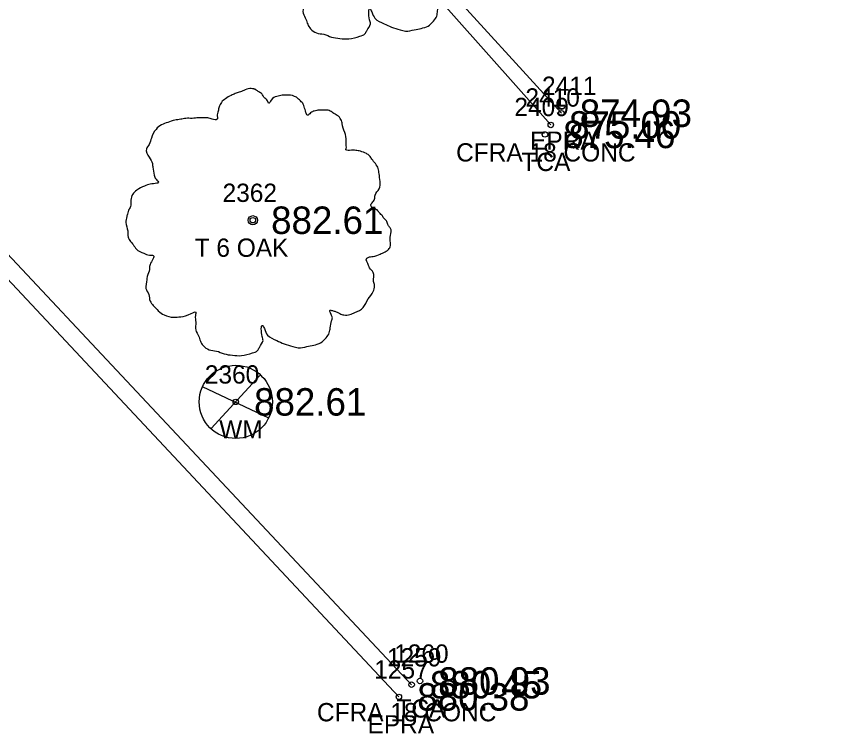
# Model space of a CAD drawing. Extents: x 1622501 to 1626664, y 1117816 to 1121579.
# Drawn here: x 1623702.07 to 1623747.27, y 1118848.61 to 1118887.8 of the extents above; entities that cross this region are included whole.
import ezdxf

# ---------------------------------------------------------------- set-up
doc = ezdxf.new("R2010")
doc.units = 0
for name, color, linetype in [('RD_EX_Conc', 7, 'Continuous'), ('RD_EX_Conc_txCode', 7, 'Continuous'), ('RD_EX_Road', 7, 'Continuous'), ('RD_EX_Road_txCode', 7, 'Continuous'), ('RD_EX_TX_Conc_ELEV', 7, 'Continuous'), ('RD_EX_TX_Road_ELEV', 7, 'Continuous'), ('RD_EX_TX_UT_ELEV', 7, 'Continuous'), ('RD_EX_TX_VEG_ELEV', 7, 'Continuous'), ('RD_EX_UT', 7, 'Continuous'), ('RD_EX_UT_txCode', 7, 'Continuous'), ('RD_EX_VEG', 7, 'Continuous'), ('RD_EX_VEG_txCode', 7, 'Continuous'), ('RD_SMD_Locator', 7, 'Continuous')]:
    doc.layers.add(name, color=color, linetype=linetype)

msp = doc.modelspace()

# ---------------------------------------------------------------- linework, layer by layer
at = {"layer": 'RD_EX_Conc'}
for points in [[(1623723.663, 1118851.276), (1623685.686, 1118891.781), (1623680.278, 1118899.276), (1623678.543, 1118902.667), (1623678.543, 1118902.667), (1623675.573, 1118911.952), (1623675.054, 1118920.354), (1623676.566, 1118930.331), (1623679.225, 1118937.184), (1623684.435, 1118944.641), (1623689.976, 1118950.418), (1623724.501, 1118984.8), (1623759.009, 1119020.42), (1623793.698, 1119055.906), (1623829.35, 1119090.862), (1623865.612, 1119125.129), (1623901.916, 1119159.181), (1623933.224, 1119188.498)], [(1623731.27, 1118881.874), (1623724.208, 1118889.844)]]:
    msp.add_lwpolyline(points, dxfattribs=at)
at = {"layer": 'RD_EX_Road'}
for points in [[(1623722.97, 1118850.612), (1623684.945, 1118891.225), (1623679.413, 1118898.675), (1623674.261, 1118911.526), (1623673.503, 1118920.185), (1623675.206, 1118930.826), (1623677.985, 1118937.822), (1623683.61, 1118945.518), (1623688.806, 1118951.265), (1623723.469, 1118985.717), (1623758.003, 1119021.43), (1623792.693, 1119056.92), (1623828.408, 1119091.915), (1623864.599, 1119126.191), (1623900.882, 1119160.216), (1623932.37, 1119189.416), (1623932.628, 1119189.219), (1623935.818, 1119192.17), (1623973.771, 1119227.767), (1623990.875, 1119243.538), (1624009.987, 1119262.018), (1624046.295, 1119296.153)], [(1623731.855, 1118882.514), (1623725.132, 1118889.887)]]:
    msp.add_lwpolyline(points, dxfattribs=at)
at = {"layer": 'RD_EX_UT'}
for p, q in [((1623712.701, 1118865.278), (1623715.369, 1118868.175)), ((1623712.22, 1118867.573), (1623715.851, 1118865.861))]:
    msp.add_line(p, q, dxfattribs=at)
msp.add_circle((1623714.054, 1118866.736), 2, dxfattribs=at)
at = {"layer": 'RD_EX_VEG'}
for centre, radius in [((1623714.985, 1118876.665), 0.25), ((1623714.973, 1118876.646), 0.0001)]:
    msp.add_circle(centre, radius, dxfattribs=at)
for points in [[(1623720.987, 1118901.145), (1623720.688, 1118901.17), (1623720.363, 1118901.07), (1623720.113, 1118900.97), (1623719.888, 1118900.895), (1623719.663, 1118900.795), (1623719.363, 1118900.62), (1623719.138, 1118900.42), (1623719.013, 1118900.17), (1623718.963, 1118899.945), (1623718.913, 1118899.671), (1623718.913, 1118899.496), (1623718.788, 1118899.471), (1623718.638, 1118899.496), (1623718.389, 1118899.571), (1623718.139, 1118899.571), (1623717.889, 1118899.571), (1623717.539, 1118899.546), (1623717.189, 1118899.546), (1623716.914, 1118899.496), (1623716.589, 1118899.446), (1623716.215, 1118899.321), (1623715.865, 1118899.196), (1623715.565, 1118898.946), (1623715.315, 1118898.471), (1623715.19, 1118898.121), (1623715.04, 1118897.871), (1623715.19, 1118897.422), (1623715.365, 1118897.072), (1623715.39, 1118896.872), (1623715.465, 1118896.447), (1623715.565, 1118896.222), (1623715.69, 1118896.022), (1623715.615, 1118895.997), (1623715.24, 1118895.947), (1623714.94, 1118895.847), (1623714.515, 1118895.622), (1623714.29, 1118895.397), (1623714.19, 1118895.073), (1623714.165, 1118894.723), (1623714.066, 1118894.523), (1623713.991, 1118894.248), (1623713.966, 1118894.173), (1623713.916, 1118893.848), (1623714.016, 1118893.398), (1623714.041, 1118893.048), (1623714.165, 1118892.824), (1623714.315, 1118892.649), (1623714.49, 1118892.399), (1623714.89, 1118892.174), (1623715.215, 1118892.074), (1623715.415, 1118892.049), (1623715.24, 1118891.549), (1623715.19, 1118891.199), (1623715.065, 1118890.799), (1623715.065, 1118890.725), (1623715.015, 1118890.25), (1623715.165, 1118889.925), (1623715.24, 1118889.55), (1623715.415, 1118889.325), (1623715.69, 1118889.025), (1623716.015, 1118888.8), (1623716.514, 1118888.675), (1623716.914, 1118888.7), (1623717.489, 1118888.875), (1623717.739, 1118888.95), (1623717.714, 1118888.775), (1623717.739, 1118888.4), (1623717.739, 1118887.976), (1623717.889, 1118887.651), (1623717.989, 1118887.376), (1623718.139, 1118887.126), (1623718.464, 1118886.901), (1623718.863, 1118886.826), (1623719.288, 1118886.676), (1623719.738, 1118886.601), (1623720.238, 1118886.576), (1623720.838, 1118886.726), (1623721.112, 1118886.851), (1623721.212, 1118887.026), (1623721.412, 1118887.401), (1623721.362, 1118887.626), (1623721.387, 1118888.226), (1623721.487, 1118888.051), (1623721.662, 1118887.701), (1623722.162, 1118887.401), (1623722.562, 1118887.226), (1623723.037, 1118887.076), (1623723.336, 1118887.001), (1623723.811, 1118887.076), (1623724.186, 1118887.151), (1623724.561, 1118887.276), (1623724.861, 1118887.551), (1623725.036, 1118887.826), (1623725.086, 1118888.101), (1623725.161, 1118888.475), (1623725.211, 1118888.65)], [(1623715.117, 1118883.832), (1623714.817, 1118883.857), (1623714.493, 1118883.757), (1623714.243, 1118883.658), (1623714.018, 1118883.583), (1623713.793, 1118883.483), (1623713.493, 1118883.308), (1623713.268, 1118883.108), (1623713.143, 1118882.858), (1623713.093, 1118882.633), (1623713.043, 1118882.358), (1623713.043, 1118882.183), (1623712.918, 1118882.158), (1623712.768, 1118882.183), (1623712.518, 1118882.258), (1623712.269, 1118882.258), (1623712.019, 1118882.258), (1623711.669, 1118882.233), (1623711.319, 1118882.233), (1623711.044, 1118882.183), (1623710.719, 1118882.133), (1623710.344, 1118882.008), (1623709.995, 1118881.883), (1623709.695, 1118881.633), (1623709.445, 1118881.159), (1623709.32, 1118880.809), (1623709.17, 1118880.559), (1623709.32, 1118880.109), (1623709.495, 1118879.759), (1623709.52, 1118879.559), (1623709.595, 1118879.135), (1623709.695, 1118878.91), (1623709.82, 1118878.71), (1623709.745, 1118878.685), (1623709.37, 1118878.635), (1623709.07, 1118878.535), (1623708.645, 1118878.31), (1623708.42, 1118878.085), (1623708.32, 1118877.76), (1623708.295, 1118877.41), (1623708.195, 1118877.21), (1623708.12, 1118876.935), (1623708.095, 1118876.86), (1623708.045, 1118876.536), (1623708.145, 1118876.086), (1623708.17, 1118875.736), (1623708.295, 1118875.511), (1623708.445, 1118875.336), (1623708.62, 1118875.086), (1623709.02, 1118874.861), (1623709.345, 1118874.761), (1623709.545, 1118874.736), (1623709.37, 1118874.237), (1623709.32, 1118873.887), (1623709.195, 1118873.487), (1623709.195, 1118873.412), (1623709.145, 1118872.937), (1623709.295, 1118872.612), (1623709.37, 1118872.238), (1623709.545, 1118872.013), (1623709.82, 1118871.713), (1623710.144, 1118871.488), (1623710.644, 1118871.363), (1623711.044, 1118871.388), (1623711.619, 1118871.563), (1623711.869, 1118871.638), (1623711.844, 1118871.463), (1623711.869, 1118871.088), (1623711.869, 1118870.663), (1623712.019, 1118870.338), (1623712.119, 1118870.063), (1623712.269, 1118869.814), (1623712.593, 1118869.589), (1623712.993, 1118869.514), (1623713.418, 1118869.364), (1623713.868, 1118869.289), (1623714.368, 1118869.264), (1623714.967, 1118869.414), (1623715.242, 1118869.539), (1623715.342, 1118869.714), (1623715.542, 1118870.088), (1623715.492, 1118870.313), (1623715.517, 1118870.913), (1623715.617, 1118870.738), (1623715.792, 1118870.388), (1623716.292, 1118870.088), (1623716.692, 1118869.914), (1623717.166, 1118869.764), (1623717.466, 1118869.689), (1623717.941, 1118869.764), (1623718.316, 1118869.839), (1623718.691, 1118869.964), (1623718.991, 1118870.238), (1623719.166, 1118870.513), (1623719.216, 1118870.788), (1623719.29, 1118871.163), (1623719.34, 1118871.338)], [(1623719.34, 1118871.338), (1623719.266, 1118871.513), (1623719.216, 1118871.763), (1623719.29, 1118871.738), (1623719.465, 1118871.688), (1623719.74, 1118871.563), (1623719.965, 1118871.488), (1623720.29, 1118871.513), (1623720.565, 1118871.613), (1623721.015, 1118871.888), (1623721.29, 1118872.362), (1623721.564, 1118872.762), (1623721.639, 1118873.087), (1623721.589, 1118873.312), (1623721.564, 1118873.812), (1623721.365, 1118874.062), (1623721.315, 1118874.187), (1623721.215, 1118874.586), (1623721.29, 1118874.636), (1623721.564, 1118874.686), (1623721.939, 1118874.811), (1623722.214, 1118874.936), (1623722.439, 1118875.111), (1623722.514, 1118875.336), (1623722.489, 1118875.736), (1623722.539, 1118876.136), (1623722.464, 1118876.286), (1623722.364, 1118876.436), (1623722.289, 1118876.636), (1623722.139, 1118876.785), (1623722.039, 1118876.935), (1623721.939, 1118877.035), (1623721.814, 1118877.185), (1623721.639, 1118877.31), (1623721.49, 1118877.36), (1623721.44, 1118877.51), (1623721.589, 1118877.71), (1623721.639, 1118877.81), (1623721.664, 1118878.035), (1623721.889, 1118878.385), (1623721.939, 1118878.785), (1623721.889, 1118879.209), (1623721.839, 1118879.484), (1623721.689, 1118879.759), (1623721.49, 1118880.009), (1623721.365, 1118880.184), (1623721.19, 1118880.309), (1623720.865, 1118880.434), (1623720.615, 1118880.484), (1623720.265, 1118880.484), (1623720.065, 1118880.534), (1623720.09, 1118880.584), (1623720.09, 1118880.734), (1623720.09, 1118881.009), (1623720.015, 1118881.458), (1623719.865, 1118881.958), (1623719.865, 1118881.983), (1623719.765, 1118882.233), (1623719.54, 1118882.433), (1623719.365, 1118882.533), (1623719.166, 1118882.658), (1623718.916, 1118882.683), (1623718.616, 1118882.683), (1623718.341, 1118882.633), (1623718.141, 1118882.533), (1623717.966, 1118882.408), (1623717.891, 1118882.558), (1623717.791, 1118882.858), (1623717.741, 1118883.008), (1623717.591, 1118883.183), (1623717.366, 1118883.383), (1623716.916, 1118883.508), (1623716.292, 1118883.433), (1623715.992, 1118883.233), (1623715.842, 1118883.058), (1623715.792, 1118883.183), (1623715.592, 1118883.383), (1623715.492, 1118883.558), (1623715.317, 1118883.683), (1623715.167, 1118883.782), (1623715.067, 1118883.832)]]:
    msp.add_spline(points, degree=3, dxfattribs=at)
at = {"layer": 'RD_SMD_Locator'}
for centre in [(1623731.855, 1118882.514), (1623731.27, 1118881.874), (1623730.951, 1118881.355), (1623714.985, 1118876.665), (1623714.054, 1118866.736), (1623723.663, 1118851.276), (1623724.12, 1118851.479), (1623722.97, 1118850.612)]:
    msp.add_circle(centre, 0.15, dxfattribs=at)

# ---------------------------------------------------------------- texts
at = {"layer": 'RD_EX_Conc_txCode'}
for s, p in [('2410', (1623729.884, 1118882.874)), ('2409', (1623729.282, 1118882.355)), ('CFRA 18 CONC', (1623726.097, 1118879.874)), ('TCA', (1623729.667, 1118879.355)), ('1260', (1623722.71, 1118852.479)), ('1259', (1623722.317, 1118852.276)), ('CFRA 18 CONC', (1623718.49, 1118849.276)), ('TCA', (1623722.836, 1118849.479))]:
    msp.add_text(s, height=1, dxfattribs=at).set_placement(p)
at = {"layer": 'RD_EX_Road_txCode'}
for s, p in [('2411', (1623730.792, 1118883.514)), ('EPRA', (1623730.138, 1118880.514)), ('1257', (1623721.624, 1118851.612)), ('EPRA', (1623721.254, 1118848.612))]:
    msp.add_text(s, height=1, dxfattribs=at).set_placement(p)
at = {"layer": 'RD_EX_TX_Conc_ELEV'}
for s, p in [('875.00', (1623732.27, 1118881.124)), ('875.46', (1623731.951, 1118880.605)), ('880.93', (1623725.12, 1118850.729)), ('880.45', (1623724.663, 1118850.526))]:
    msp.add_text(s, height=1.5, dxfattribs=at).set_placement(p)
at = {"layer": 'RD_EX_TX_Road_ELEV'}
for s, p in [('874.93', (1623732.855, 1118881.764)), ('880.38', (1623723.97, 1118849.862))]:
    msp.add_text(s, height=1.5, dxfattribs=at).set_placement(p)
at = {"layer": 'RD_EX_TX_UT_ELEV'}
msp.add_text('882.61', height=1.5, dxfattribs=at).set_placement((1623715.054, 1118865.986))
at = {"layer": 'RD_EX_TX_VEG_ELEV'}
msp.add_text('882.61', height=1.5, dxfattribs=at).set_placement((1623715.985, 1118875.915))
at = {"layer": 'RD_EX_UT_txCode'}
for s, p in [('2360', (1623712.361, 1118867.736)), ('WM', (1623713.148, 1118864.736))]:
    msp.add_text(s, height=1, dxfattribs=at).set_placement(p)
at = {"layer": 'RD_EX_VEG_txCode'}
for s, p in [('2362', (1623713.332, 1118877.665)), ('T 6 OAK', (1623711.804, 1118874.665))]:
    msp.add_text(s, height=1, dxfattribs=at).set_placement(p)

doc.saveas('drawing.dxf')
